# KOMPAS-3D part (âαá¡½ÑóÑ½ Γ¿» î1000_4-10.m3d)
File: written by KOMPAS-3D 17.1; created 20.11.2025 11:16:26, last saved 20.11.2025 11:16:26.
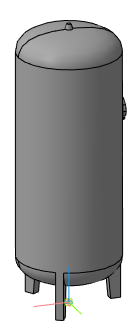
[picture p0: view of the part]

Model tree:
1. Операция без истории:2

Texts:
  REVIT MATERIAL OVERRIDDEN
  REVIT MATERIAL ID
  REVIT SUBCATEGORY ID
  REVIT CATEGORY ID
  REVIT ELEMENT ID
  REVIT BREP TAG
